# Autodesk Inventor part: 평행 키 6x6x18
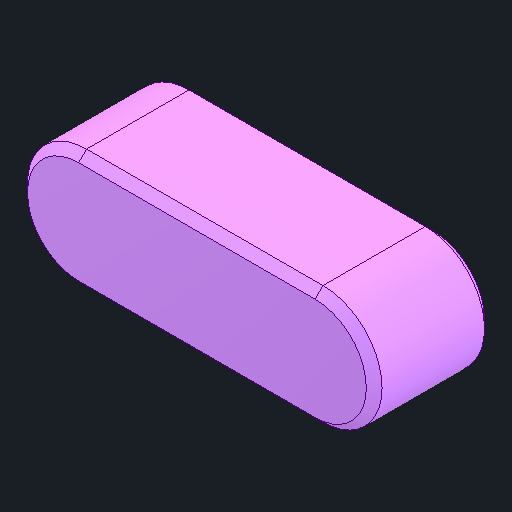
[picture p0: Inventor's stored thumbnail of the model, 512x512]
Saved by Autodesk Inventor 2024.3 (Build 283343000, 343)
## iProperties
Created: 2025-07
Part Number: 평행 키 6x6x18
Material: 강철, 연강
Description: 키 및 해당 키홈
Document SubType Name: Modeling
Designer: user
Density: 7.85 g/cm^3
Appearance: 기본값
Author: jhkim
Sending System: Autodesk Inventor 2026
Preprocessor: ST-DEVELOPER v20.1
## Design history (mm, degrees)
feature "Solid1"
node "솔리드1"
